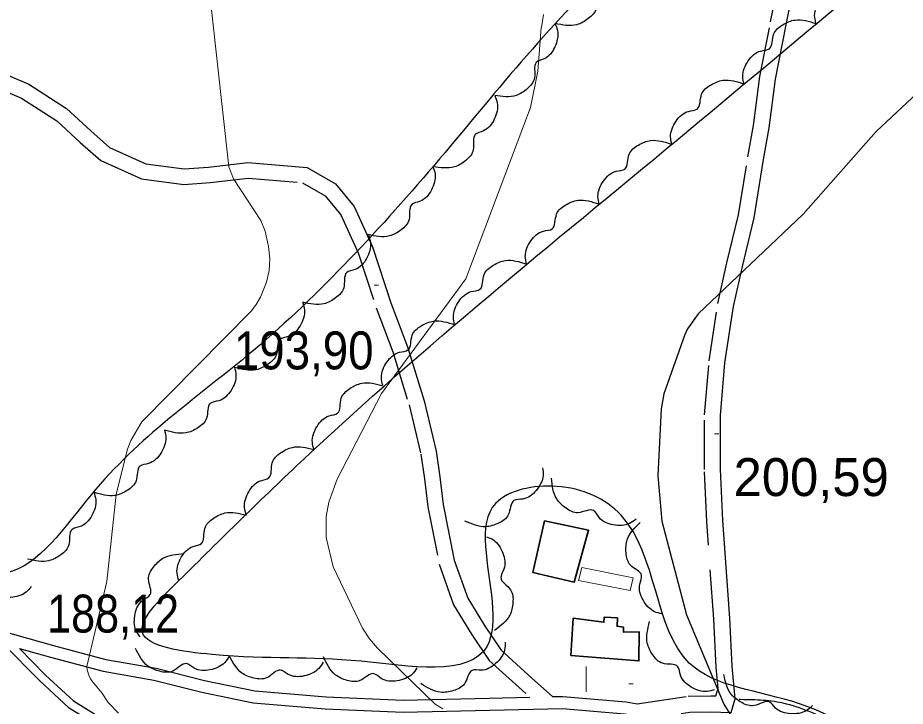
# Model space of a CAD drawing. Extents: x 480269 to 484877, y 4383588 to 4386804.
# Drawn here: x 482562.7 to 482767.4, y 4385614.3 to 4385773.1 of the extents above; entities that cross this region are included whole.
import ezdxf

# ---------------------------------------------------------------- set-up
doc = ezdxf.new("R2010")
doc.units = 0
doc.header["$LTSCALE"] = 3.8
doc.linetypes.add('LONG_DASHED', pattern=[7.5, 6, -1.5])
doc.linetypes.add('MEDIUM_DASHED', pattern=[4.5, 3, -1.5])
for name, color, linetype, lineweight in [('27', 7, 'Continuous', 25), ('38', 7, 'Continuous', 25), ('47', 7, 'Continuous', 35), ('51', 7, 'Continuous', 13), ('7', 7, 'Continuous', 13), ('8', 7, 'Continuous', 25), ('9', 7, 'Continuous', 13)]:
    doc.layers.add(name, color=color, linetype=linetype, lineweight=lineweight)

msp = doc.modelspace()

# ---------------------------------------------------------------- linework, layer by layer
at = {"layer": '27'}
for points in [[(482928.34, 4385924.89), (482922.57, 4385923.15), (482885.78, 4385895.73), (482830.19, 4385870.67), (482783.99, 4385846.38), (482748.76, 4385821.32), (482700.22, 4385785.28), (482658.72, 4385739.07), (482615.66, 4385695.2), (482579.64, 4385663.09), (482560.07, 4385645.07), (482539.71, 4385649.77), (482459.85, 4385672.49), (482360.42, 4385703.82), (482306.4, 4385727.32), (482257.85, 4385789.2), (482191.3, 4385880.85), (482166.25, 4385912.96), (482169.38, 4385923.15), (482197.57, 4385932.55), (482218.71, 4385942.73), (482235.93, 4385961.53), (482260.99, 4385957.61), (482288.39, 4385973.28), (482296.22, 4385991.3), (482306.4, 4385999.91), (482324.4, 4386001.48), (482354.16, 4385995.21), (482372.16, 4385973.28), (482387.82, 4385970.15), (482414.44, 4385988.16), (482434.02, 4385990.51), (482466.12, 4385956.05), (482473.95, 4385954.08)], [(482599.89, 4385643.3), (482628.86, 4385671.49), (482714.99, 4385745.13), (482794.85, 4385810.14), (482867.67, 4385855.58), (482941.27, 4385895.53), (482964.76, 4385912.76), (482973.37, 4385911.19), (482981.98, 4385879.86), (482998.42, 4385827.38), (483006.25, 4385814.84), (483025.83, 4385810.93), (483050.88, 4385818.76), (483058.71, 4385808.58), (483056.36, 4385779.59), (483052.45, 4385741.21), (483034.44, 4385691.86), (483035.22, 4385677.76), (483043.84, 4385669.93), (483091.6, 4385655.04), (483126.05, 4385633.11), (483147.97, 4385609.61), (483156.58, 4385589.25), (483155.8, 4385568.88), (483155.02, 4385552.43), (483155.02, 4385532.85), (483155.02, 4385519.53), (483152.67, 4385510.13)], [(482701.55, 4385787.58), (482702.05, 4385785.88), (482701.23, 4385782.17), (482698.62, 4385779.56), (482696.71, 4385778.8), (482696.12, 4385775.3), (482694.3, 4385772.93), (482691.63, 4385771.52), (482686.67, 4385771.78)], [(482746.75, 4385771.89), (482746.49, 4385773.64), (482747.8, 4385777.2), (482750.74, 4385779.44), (482752.73, 4385779.93), (482753.8, 4385783.33), (482755.92, 4385785.43), (482758.76, 4385786.47), (482763.63, 4385785.53)], [(482686.58, 4385771.87), (482687.18, 4385770.2), (482686.59, 4385766.45), (482684.15, 4385763.68), (482682.29, 4385762.81), (482681.92, 4385759.27), (482680.25, 4385756.79), (482677.67, 4385755.22), (482672.71, 4385755.18)], [(482730.2, 4385757.85), (482729.91, 4385759.6), (482731.17, 4385763.18), (482734.07, 4385765.46), (482736.06, 4385765.99), (482737.07, 4385769.4), (482739.15, 4385771.53), (482741.97, 4385772.61), (482746.86, 4385771.76)], [(482713.56, 4385743.93), (482713.26, 4385745.68), (482714.52, 4385749.26), (482717.42, 4385751.54), (482719.41, 4385752.07), (482720.42, 4385755.48), (482722.5, 4385757.61), (482725.33, 4385758.7), (482730.21, 4385757.84)], [(482672.73, 4385755.16), (482673.29, 4385753.47), (482672.62, 4385749.74), (482670.11, 4385747.03), (482668.23, 4385746.2), (482667.77, 4385742.67), (482666.05, 4385740.24), (482663.43, 4385738.73), (482658.47, 4385738.8)], [(482696.8, 4385730.14), (482696.52, 4385731.9), (482697.8, 4385735.47), (482700.72, 4385737.73), (482702.71, 4385738.24), (482703.74, 4385741.64), (482705.84, 4385743.76), (482708.67, 4385744.82), (482713.55, 4385743.93)], [(482658.47, 4385738.81), (482658.96, 4385737.1), (482658.11, 4385733.4), (482655.49, 4385730.8), (482653.57, 4385730.06), (482652.96, 4385726.56), (482651.13, 4385724.2), (482648.45, 4385722.8), (482643.49, 4385723.1)], [(482680.05, 4385716.35), (482679.77, 4385718.1), (482681.05, 4385721.67), (482683.97, 4385723.93), (482685.96, 4385724.44), (482686.99, 4385727.84), (482689.09, 4385729.96), (482691.93, 4385731.03), (482696.81, 4385730.14)], [(482643.6, 4385723), (482644.06, 4385721.29), (482643.16, 4385717.6), (482640.49, 4385715.05), (482638.57, 4385714.33), (482637.9, 4385710.84), (482636.03, 4385708.51), (482633.33, 4385707.15), (482628.38, 4385707.53)], [(482663.48, 4385702.33), (482663.18, 4385704.08), (482664.42, 4385707.67), (482667.32, 4385709.96), (482669.3, 4385710.5), (482670.29, 4385713.91), (482672.37, 4385716.05), (482675.19, 4385717.15), (482680.08, 4385716.31)], [(482628.44, 4385707.47), (482628.85, 4385705.74), (482627.84, 4385702.09), (482625.1, 4385699.61), (482623.16, 4385698.95), (482622.39, 4385695.48), (482620.45, 4385693.21), (482617.71, 4385691.93), (482612.78, 4385692.45)], [(482646.89, 4385688.35), (482646.59, 4385690.1), (482647.83, 4385693.68), (482650.73, 4385695.97), (482652.71, 4385696.51), (482653.7, 4385699.92), (482655.78, 4385702.07), (482658.6, 4385703.16), (482663.49, 4385702.33)], [(482612.7, 4385692.54), (482613.05, 4385690.8), (482611.92, 4385687.18), (482609.1, 4385684.79), (482607.14, 4385684.19), (482606.26, 4385680.75), (482604.25, 4385678.54), (482601.46, 4385677.36), (482596.55, 4385678.04)], [(482631.05, 4385673.51), (482630.67, 4385675.24), (482631.75, 4385678.88), (482634.54, 4385681.3), (482636.5, 4385681.92), (482637.34, 4385685.38), (482639.32, 4385687.61), (482642.08, 4385688.83), (482647, 4385688.22)], [(482542.34, 4385576.13), (482572.3, 4385598.45), (482613.4, 4385606.67), (482669.38, 4385601.97), (482699.92, 4385603.54), (482716.36, 4385597.27), (482706.58, 4385589.44), (482664.3, 4385586.7), (482640.81, 4385577.69), (482659.6, 4385562.02), (482674.47, 4385548.71), (482701.09, 4385543.22), (482742.98, 4385528.73), (482771.17, 4385497.4), (482787.61, 4385488.78), (482810.32, 4385489.57), (482832.24, 4385507.97), (482853.77, 4385510.32), (482862.39, 4385502.1), (482893.71, 4385505.62), (482910.54, 4385507.58), (482910.93, 4385544.79), (482907.8, 4385570.25), (482898.79, 4385625.47), (482891.36, 4385663.07), (482883.53, 4385676.78), (482864.34, 4385664.64), (482827.54, 4385621.56), (482795.44, 4385594.92), (482777.04, 4385578.47), (482768.43, 4385580.04), (482764.52, 4385594.53), (482742.98, 4385614.9), (482717.54, 4385624.3), (482701.88, 4385658.37), (482687, 4385665.03), (482672.91, 4385661.11), (482672.12, 4385638.4), (482670.95, 4385628.21), (482641.98, 4385624.69), (482607.53, 4385626.26), (482591.48, 4385631.35), (482599.89, 4385643.3)], [(482596.55, 4385678.04), (482596.89, 4385676.3), (482595.73, 4385672.69), (482592.89, 4385670.32), (482590.92, 4385669.74), (482590.01, 4385666.31), (482587.99, 4385664.12), (482585.19, 4385662.95), (482580.29, 4385663.67)], [(482615.44, 4385658.43), (482615.02, 4385660.16), (482616, 4385663.82), (482618.72, 4385666.32), (482620.66, 4385666.99), (482621.41, 4385670.47), (482623.33, 4385672.75), (482626.06, 4385674.04), (482631, 4385673.56)], [(482683.75, 4385669.33), (482683.87, 4385667.56), (482682.29, 4385664.11), (482679.18, 4385662.11), (482677.16, 4385661.77), (482675.84, 4385658.47), (482673.56, 4385656.54), (482670.65, 4385655.73), (482665.86, 4385657.04)], [(482705.31, 4385657.46), (482703.83, 4385656.48), (482700.05, 4385656.15), (482696.78, 4385657.86), (482695.49, 4385659.46), (482691.96, 4385658.97), (482689.16, 4385660), (482687.01, 4385662.13), (482685.79, 4385666.93)], [(482580.25, 4385663.71), (482580.71, 4385661.99), (482579.8, 4385658.31), (482577.13, 4385655.76), (482575.2, 4385655.05), (482574.52, 4385651.56), (482572.65, 4385649.24), (482569.94, 4385647.89), (482564.99, 4385648.28)], [(482599.89, 4385643.3), (482599.47, 4385645.02), (482600.45, 4385648.69), (482603.17, 4385651.18), (482605.11, 4385651.86), (482605.86, 4385655.33), (482607.78, 4385657.62), (482610.51, 4385658.91), (482615.45, 4385658.43)], [(482711.27, 4385635.62), (482709.57, 4385636.14), (482706.92, 4385638.86), (482706.17, 4385642.47), (482706.58, 4385644.49), (482703.98, 4385646.91), (482703, 4385649.72), (482703.28, 4385652.73), (482706.22, 4385656.73)], [(482670.79, 4385653.44), (482672.4, 4385652.68), (482674.62, 4385649.6), (482674.83, 4385645.91), (482674.13, 4385643.99), (482676.35, 4385641.21), (482676.91, 4385638.28), (482676.18, 4385635.34), (482672.69, 4385631.82)], [(482590.95, 4385630.34), (482590.01, 4385631.84), (482589.81, 4385635.63), (482591.63, 4385638.85), (482593.26, 4385640.09), (482592.9, 4385643.62), (482594.02, 4385646.39), (482596.22, 4385648.47), (482601.06, 4385649.53)], [(482565.86, 4385641.98), (482564.67, 4385640.66), (482561.09, 4385639.4), (482557.5, 4385640.25), (482555.85, 4385641.47), (482552.56, 4385640.13), (482549.59, 4385640.42), (482546.98, 4385641.95), (482544.6, 4385646.31)], [(482723.42, 4385618.15), (482721.69, 4385617.74), (482718.03, 4385618.76), (482715.56, 4385621.5), (482714.91, 4385623.45), (482711.44, 4385624.23), (482709.17, 4385626.17), (482707.9, 4385628.91), (482708.43, 4385633.85)], [(482675.13, 4385629.11), (482675, 4385627.34), (482672.93, 4385624.16), (482669.57, 4385622.63), (482667.52, 4385622.59), (482665.73, 4385619.52), (482663.2, 4385617.94), (482660.2, 4385617.56), (482655.65, 4385619.55)], [(482611.49, 4385625.85), (482610.46, 4385624.39), (482607.06, 4385622.73), (482603.39, 4385623.14), (482601.6, 4385624.16), (482598.49, 4385622.44), (482595.51, 4385622.38), (482592.74, 4385623.59), (482589.86, 4385627.63)], [(482633.14, 4385624.49), (482632.14, 4385623.02), (482628.75, 4385621.31), (482625.08, 4385621.68), (482623.28, 4385622.67), (482620.2, 4385620.91), (482617.21, 4385620.82), (482614.43, 4385621.99), (482611.5, 4385626)], [(482654.77, 4385623.15), (482653.69, 4385621.74), (482650.22, 4385620.2), (482646.57, 4385620.75), (482644.83, 4385621.84), (482641.65, 4385620.24), (482638.67, 4385620.29), (482635.95, 4385621.61), (482633.22, 4385625.76)], [(482746, 4385614.5), (482744.64, 4385613.35), (482740.92, 4385612.59), (482737.48, 4385613.92), (482736.01, 4385615.35), (482732.56, 4385614.47), (482729.66, 4385615.17), (482727.29, 4385617.03), (482725.52, 4385621.67)]]:
    msp.add_spline(points, degree=3, dxfattribs=at)
at = {"layer": '38', "linetype": 'MEDIUM_DASHED'}
for points in [[(482705.59, 4385614.87), (482717.36, 4385616.66), (482722.54, 4385616.76), (482723.72, 4385616.71), (482724.25, 4385618.4), (482723.81, 4385623.32), (482723.23, 4385634.42), (482721.62, 4385656.97), (482721.1, 4385668.95), (482721.1, 4385681.56), (482722.14, 4385693.97), (482724.17, 4385707.2), (482726.27, 4385716.59), (482728.95, 4385727.7), (482731.08, 4385741.07), (482732.38, 4385748.31), (482733.83, 4385759.6), (482736.34, 4385772.19), (482738.87, 4385785.2)], [(482556.38, 4385757.66), (482563.6, 4385754.6), (482571.78, 4385749.37), (482577.16, 4385744.39), (482581.91, 4385740.17), (482591.25, 4385735.97), (482601.02, 4385734.67), (482607.08, 4385735.11), (482615.84, 4385736.16), (482628.4, 4385735.08), (482633.65, 4385732.04), (482637.2, 4385727.65), (482641.23, 4385718.94), (482645.41, 4385706.19), (482649.19, 4385696.08), (482652.97, 4385683.85), (482655.68, 4385672.46), (482656.53, 4385666.77), (482657.3, 4385660.33), (482659.9, 4385647.06), (482663.25, 4385637.71), (482667.35, 4385630.98), (482671.43, 4385624.88), (482680.85, 4385616.4)], [(482563.14, 4385627.63), (482569.16, 4385621.53), (482575.61, 4385615.55), (482582.91, 4385611.04), (482589.5, 4385604.35), (482600.75, 4385592.81), (482604.49, 4385587.48), (482608.39, 4385583.43), (482618.11, 4385581.15), (482627.48, 4385581.36), (482638.59, 4385580.93), (482649.8, 4385580.41), (482653.37, 4385580.49), (482668.05, 4385578.87), (482670.62, 4385578.73), (482677.3, 4385574.83), (482677.73, 4385567.68), (482677.72, 4385562.73), (482678.3, 4385558.8), (482679.25, 4385555.52), (482683.36, 4385553.27), (482684.95, 4385553.36), (482692.33, 4385554.95)]]:
    msp.add_lwpolyline(points, dxfattribs=at)
at = {"layer": '38'}
for points in [[(482715.73, 4385612.69), (482717.67, 4385612.97), (482722.51, 4385613.07), (482727.22, 4385612.9), (482728.17, 4385616.01), (482727.5, 4385623.57), (482726.92, 4385634.65), (482725.31, 4385657.18), (482724.79, 4385669.03), (482724.79, 4385681.41), (482725.81, 4385693.55), (482727.79, 4385706.52), (482729.86, 4385715.76), (482732.57, 4385726.99), (482734.71, 4385740.46), (482736.03, 4385747.75), (482737.47, 4385759), (482739.95, 4385771.48), (482742.5, 4385784.58)], [(482557.48, 4385761.09), (482565.28, 4385757.78), (482573.99, 4385752.21), (482579.58, 4385747.05), (482583.88, 4385743.22), (482592.24, 4385739.46), (482601.13, 4385738.28), (482606.73, 4385738.68), (482615.78, 4385739.77), (482629.5, 4385738.59), (482636.01, 4385734.82), (482640.27, 4385729.57), (482644.57, 4385720.26), (482648.8, 4385707.38), (482652.59, 4385697.24), (482656.43, 4385684.8), (482659.21, 4385673.15), (482660.09, 4385667.25), (482660.84, 4385660.89), (482663.37, 4385648.02), (482666.51, 4385639.27), (482670.38, 4385632.92), (482674.17, 4385627.24), (482681.3, 4385620.82), (482686.01, 4385616.54)], [(482313.81, 4385715.06), (482332.03, 4385708.34), (482357.79, 4385698.89), (482384.55, 4385689.31), (482408.68, 4385680.69), (482437.93, 4385669.22), (482466.74, 4385659.16), (482496.44, 4385650.04), (482519.53, 4385643.58), (482538.67, 4385638.31), (482552.89, 4385633.38), (482570.99, 4385628.3), (482583.05, 4385625.13), (482594.66, 4385623.08), (482605.8, 4385620.28), (482617.39, 4385617.9), (482633.82, 4385616.47), (482651.61, 4385615.7), (482671.51, 4385616.16), (482680.85, 4385616.4)], [(482559.47, 4385628.65), (482567.85, 4385620.18), (482574.46, 4385614.05), (482581.73, 4385609.56), (482588.16, 4385603.03), (482599.3, 4385591.61), (482603.04, 4385586.29), (482607.42, 4385581.73), (482617.91, 4385579.27), (482627.47, 4385579.48), (482638.51, 4385579.05), (482649.78, 4385578.53), (482653.28, 4385578.61), (482667.89, 4385577), (482670.07, 4385576.88), (482675.49, 4385573.71), (482675.85, 4385567.62), (482675.84, 4385562.6), (482676.47, 4385558.4), (482677.67, 4385554.25), (482682.93, 4385551.36), (482685.21, 4385551.5), (482692.72, 4385553.12)], [(482563.14, 4385627.63), (482570.26, 4385625.63), (482582.46, 4385622.42), (482594.08, 4385620.36), (482605.18, 4385617.58), (482616.99, 4385615.15), (482633.63, 4385613.7), (482651.58, 4385612.93), (482671.58, 4385613.39), (482688.31, 4385613.82), (482702.64, 4385612.58), (482712.86, 4385610.76), (482728.74, 4385605.19)], [(482686.01, 4385616.54), (482688.4, 4385616.59), (482703, 4385615.33), (482705.59, 4385614.87)]]:
    msp.add_lwpolyline(points, dxfattribs=at)
at = {"layer": '38', "linetype": 'LONG_DASHED'}
for points in [[(482744.29, 4385798.04), (482751.76, 4385801.34), (482769.09, 4385802.98), (482786.38, 4385797.29), (482808.74, 4385792.77), (482825.58, 4385793.37), (482843.25, 4385794.8), (482854.92, 4385794.68), (482863.36, 4385791.69), (482870.36, 4385785.68), (482869.92, 4385782.24), (482869.67, 4385772.3), (482873.58, 4385762.53), (482880.22, 4385746.55), (482883.53, 4385738.15), (482891.02, 4385720.62), (482898.5, 4385699.42), (482905.2, 4385684.64), (482910.7, 4385676.09), (482920.17, 4385664.3), (482923.56, 4385658.81), (482929.98, 4385637.62), (482930.83, 4385636.68), (482931.13, 4385618.04), (482931.31, 4385599.34), (482930.96, 4385592.88), (482932.31, 4385542.38), (482934.1, 4385533.92)], [(482855.09, 4385515.89), (482844.14, 4385527.45), (482831.22, 4385543.33), (482817.45, 4385557.47), (482804.35, 4385573.28), (482795.53, 4385582.48), (482788.95, 4385587.93), (482779.98, 4385591.32), (482762.14, 4385604.06), (482750.3, 4385610.79), (482738.47, 4385615.18), (482728.12, 4385615.85)]]:
    msp.add_spline(points, degree=3, dxfattribs=at)
at = {"layer": '47'}
for points in [[(482684.16, 4385657.06), (482681.51, 4385645.16), (482691.07, 4385642.94), (482694.37, 4385654.94)], [(482690.78, 4385634.63), (482690.24, 4385626.04), (482705.98, 4385624.79), (482706.03, 4385631.46), (482702.43, 4385631.4), (482702.38, 4385632.58), (482700.94, 4385632.79), (482701, 4385634.71), (482697.97, 4385634.88), (482697.91, 4385633.7)]]:
    msp.add_lwpolyline(points, close=True, dxfattribs=at)
at = {"layer": '47', "lineweight": 13}
msp.add_lwpolyline([(482692.78, 4385646.33), (482704.61, 4385643.92), (482703.93, 4385641.05), (482692, 4385643.31)], close=True, dxfattribs=at)
at = {"layer": '51'}
msp.add_line((482693.8, 4385623.47), (482693.78, 4385617.66), dxfattribs=at)
at = {"layer": '7'}
for p, q in [((482644.93, 4385711.45), (482645.93, 4385711.45)), ((482723.36, 4385677.18), (482724.36, 4385677.18)), ((482703.62, 4385619.47), (482704.62, 4385619.47))]:
    msp.add_line(p, q, dxfattribs=at)
at = {"layer": '8'}
msp.add_lwpolyline([(482974.08, 4385962.84), (482908.38, 4385890.3), (482901.16, 4385884.48), (482897.39, 4385882.24), (482856.09, 4385865.5), (482845.35, 4385858.2), (482842.41, 4385855.01), (482838.9, 4385849.82), (482837.2, 4385845.61), (482822.15, 4385818.3), (482786.6, 4385771.14), (482760.71, 4385746.91), (482743.87, 4385727.8), (482719.64, 4385704.84), (482717.19, 4385701.35), (482716.5, 4385699.87), (482711.72, 4385686.41), (482711.08, 4385682.92), (482710.31, 4385667.5), (482711.27, 4385657.05), (482716.96, 4385635.42), (482725.53, 4385614.77), (482731.4, 4385605.41), (482741.47, 4385596.43)], dxfattribs=at)
at = {"layer": '9'}
for points in [[(482607.43, 4385774.96), (482611.44, 4385738.74), (482612.52, 4385735.96), (482618.78, 4385726.4), (482619.77, 4385723.88), (482620.56, 4385720.38), (482620.83, 4385717.52), (482620.67, 4385714.86), (482620.09, 4385712.15), (482618.73, 4385708.72), (482617.74, 4385707), (482616.65, 4385705.53), (482591.38, 4385679.96), (482588.83, 4385675.64), (482588.08, 4385673.65), (482585.46, 4385663.25), (482583.24, 4385643.12), (482578.69, 4385623.46), (482578.75, 4385622.73), (482578.8, 4385622.52), (482579.11, 4385621.48), (482579.52, 4385620.63), (482579.83, 4385620.17), (482582.14, 4385617.45), (482583.6, 4385615.22), (482585.95, 4385612.73)], [(482683.99, 4385773.91), (482683.47, 4385770.86), (482683.46, 4385770.85), (482682.66, 4385760.78), (482680.95, 4385752.4), (482666.06, 4385712.93), (482646.62, 4385686.5), (482636.4, 4385666.72), (482634.45, 4385661.38), (482634.44, 4385661.37), (482633.88, 4385658.08), (482633.83, 4385653.24), (482635.49, 4385646.51), (482642.25, 4385632.34), (482643.87, 4385629.89), (482645.71, 4385627.71), (482659, 4385614.8), (482660.72, 4385613.72)]]:
    msp.add_lwpolyline(points, dxfattribs=at)

# ---------------------------------------------------------------- texts
at = {"layer": '7'}
for s, width, p in [('193,90', 0.9, (482612.57, 4385692.03)), ('188,12', 0.85, (482569.51, 4385631.32))]:
    msp.add_text(s, height=8.75, dxfattribs=dict(at, width=width)).set_placement(p)
msp.add_text('200,59', height=8.75, dxfattribs=at).set_placement((482727.8, 4385662.81))

doc.saveas('drawing.dxf')
